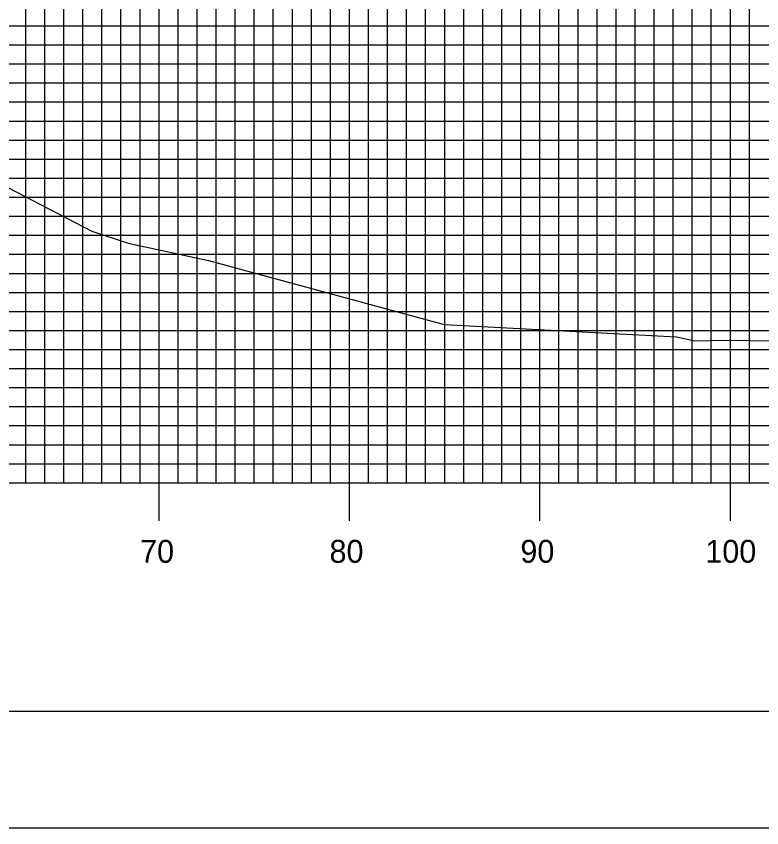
# Model space of a CAD drawing. Extents: x 860258 to 860601, y 364765 to 364985.
# Drawn here: x 860486.4 to 860525.55, y 364765.18 to 364807.8 of the extents above; entities that cross this region are included whole.
import ezdxf

# ---------------------------------------------------------------- set-up
doc = ezdxf.new("R2010")
doc.units = 0
for name, color, linetype in [('BORDER', 7, 'Continuous'), ('H_V ANNOTATION', 7, 'Continuous'), ('MAJOR', 7, 'Continuous'), ('MINOR', 7, 'Continuous'), ('PLOT BOUNDARY', 7, 'Continuous'), ('S_Roadway_Centerline', 7, 'Continuous')]:
    doc.layers.add(name, color=color, linetype=linetype)

msp = doc.modelspace()

# ---------------------------------------------------------------- linework, layer by layer
at = {"layer": 'BORDER'}
msp.add_lwpolyline([(860274.299, 364771.302), (860594.299, 364771.302), (860594.299, 364981.302), (860274.299, 364981.302)], close=True, dxfattribs=at)
at = {"layer": 'MAJOR'}
for p, q in [((860493.899, 364783.302), (860493.899, 364833.302)), ((860503.899, 364783.302), (860503.899, 364833.302)), ((860513.899, 364783.302), (860513.899, 364833.302)), ((860523.899, 364783.302), (860523.899, 364833.302)), ((860283.899, 364803.302), (860563.899, 364803.302)), ((860283.899, 364798.302), (860563.899, 364798.302)), ((860283.899, 364793.302), (860563.899, 364793.302)), ((860283.899, 364788.302), (860563.899, 364788.302)), ((860283.899, 364783.302), (860563.899, 364783.302)), ((860283.899, 364783.302), (860563.899, 364783.302)), ((860493.899, 364781.298), (860493.899, 364783.302)), ((860503.899, 364781.298), (860503.899, 364783.302)), ((860513.899, 364781.298), (860513.899, 364783.302)), ((860523.899, 364781.298), (860523.899, 364783.302))]:
    msp.add_line(p, q, dxfattribs=at)
at = {"layer": 'MINOR'}
for p, q in [((860486.899, 364783.302), (860486.899, 364833.302)), ((860487.899, 364783.302), (860487.899, 364833.302)), ((860488.899, 364783.302), (860488.899, 364833.302)), ((860489.899, 364783.302), (860489.899, 364833.302)), ((860490.899, 364783.302), (860490.899, 364833.302)), ((860491.899, 364783.302), (860491.899, 364833.302)), ((860492.899, 364783.302), (860492.899, 364833.302)), ((860494.899, 364783.302), (860494.899, 364833.302)), ((860495.899, 364783.302), (860495.899, 364833.302)), ((860496.899, 364783.302), (860496.899, 364833.302)), ((860497.899, 364783.302), (860497.899, 364833.302)), ((860498.899, 364783.302), (860498.899, 364833.302)), ((860499.899, 364783.302), (860499.899, 364833.302)), ((860500.899, 364783.302), (860500.899, 364833.302)), ((860501.899, 364783.302), (860501.899, 364833.302)), ((860502.899, 364783.302), (860502.899, 364833.302)), ((860504.899, 364783.302), (860504.899, 364833.302)), ((860505.899, 364783.302), (860505.899, 364833.302)), ((860506.899, 364783.302), (860506.899, 364833.302)), ((860507.899, 364783.302), (860507.899, 364833.302)), ((860508.899, 364783.302), (860508.899, 364833.302)), ((860509.899, 364783.302), (860509.899, 364833.302)), ((860510.899, 364783.302), (860510.899, 364833.302)), ((860511.899, 364783.302), (860511.899, 364833.302)), ((860512.899, 364783.302), (860512.899, 364833.302)), ((860514.899, 364783.302), (860514.899, 364833.302)), ((860515.899, 364783.302), (860515.899, 364833.302)), ((860516.899, 364783.302), (860516.899, 364833.302)), ((860517.899, 364783.302), (860517.899, 364833.302)), ((860518.899, 364783.302), (860518.899, 364833.302)), ((860519.899, 364783.302), (860519.899, 364833.302)), ((860520.899, 364783.302), (860520.899, 364833.302)), ((860521.899, 364783.302), (860521.899, 364833.302)), ((860522.899, 364783.302), (860522.899, 364833.302)), ((860524.899, 364783.302), (860524.899, 364833.302)), ((860283.899, 364807.302), (860563.899, 364807.302)), ((860283.899, 364806.302), (860563.899, 364806.302)), ((860283.899, 364805.302), (860563.899, 364805.302)), ((860283.899, 364804.302), (860563.899, 364804.302)), ((860283.899, 364802.302), (860563.899, 364802.302)), ((860283.899, 364801.302), (860563.899, 364801.302)), ((860283.899, 364800.302), (860563.899, 364800.302)), ((860283.899, 364799.302), (860563.899, 364799.302)), ((860283.899, 364797.302), (860563.899, 364797.302)), ((860283.899, 364796.302), (860563.899, 364796.302)), ((860283.899, 364795.302), (860563.899, 364795.302)), ((860283.899, 364794.302), (860563.899, 364794.302)), ((860283.899, 364792.302), (860563.899, 364792.302)), ((860283.899, 364791.302), (860563.899, 364791.302)), ((860283.899, 364790.302), (860563.899, 364790.302)), ((860283.899, 364789.302), (860563.899, 364789.302)), ((860283.899, 364787.302), (860563.899, 364787.302)), ((860283.899, 364786.302), (860563.899, 364786.302)), ((860283.899, 364785.302), (860563.899, 364785.302)), ((860283.899, 364784.302), (860563.899, 364784.302))]:
    msp.add_line(p, q, dxfattribs=at)
at = {"layer": 'PLOT BOUNDARY'}
msp.add_lwpolyline([(860258.113, 364765.184), (860598.113, 364765.184), (860598.113, 364985.184), (860258.113, 364985.184)], close=True, dxfattribs=at)
at = {"layer": 'S_Roadway_Centerline'}
msp.add_lwpolyline([(860432, 364824.886), (860461.596, 364810.794), (860467.531, 364807.889), (860475.668, 364804.034), (860477.481, 364803.206), (860490.368, 364796.521), (860492.278, 364795.878), (860496.494, 364794.981), (860508.871, 364791.612), (860521.066, 364790.974), (860522.026, 364790.759), (860523.549, 364790.784), (860539.157, 364790.595), (860543.349, 364791.046), (860554.313, 364791.642), (860562.727, 364791.849), (860563.899, 364791.889)], dxfattribs=at)

# ---------------------------------------------------------------- texts
at = {"layer": 'H_V ANNOTATION'}
for s, p in [('70', (860492.903, 364779.102)), ('80', (860502.85, 364779.102)), ('90', (860512.872, 364779.102)), ('100', (860522.583, 364779.102))]:
    msp.add_text(s, height=1.2, dxfattribs=at).set_placement(p)

doc.saveas('drawing.dxf')
